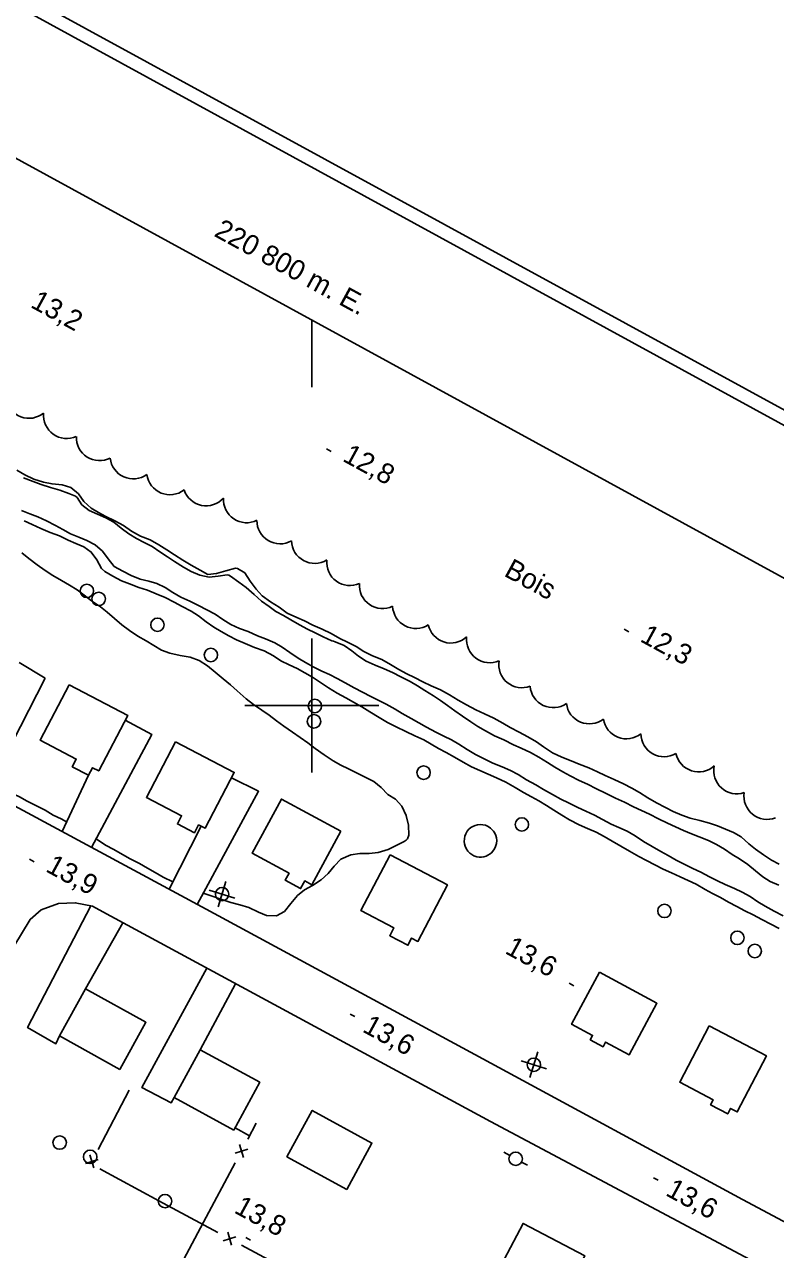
# Model space of a CAD drawing. Extents: x 219136 to 222520, y 5421589 to 5424530.
# Drawn here: x 220757.1 to 220869.2, y 5423918.8 to 5424101.6 of the extents above; entities that cross this region are included whole.
import ezdxf

# ---------------------------------------------------------------- set-up
doc = ezdxf.new("R2010")
doc.units = 0
for name, color, linetype in [('Level 19', 7, 'Continuous'), ('Level 2', 7, 'Continuous'), ('Level 21', 7, 'Continuous'), ('Level 3', 7, 'Continuous'), ('Level 31', 7, 'Continuous'), ('Level 36', 7, 'Continuous'), ('Level 37', 7, 'Continuous'), ('Level 4', 7, 'Continuous'), ('Level 44', 7, 'Continuous'), ('Level 60', 7, 'Continuous'), ('Level 61', 7, 'Continuous')]:
    doc.layers.add(name, color=color, linetype=linetype)

msp = doc.modelspace()

# ---------------------------------------------------------------- linework, layer by layer
at = {"layer": 'Level 19'}
for points in [[(220760.24, 5424004.07), (220756.33, 5424006.39)], [(220751.55, 5423987.22), (220760.24, 5424004.07)], [(220767.14, 5423978.82), (220776.12, 5423995.67), (220772.17, 5423997.8)], [(220766.7, 5423989.58), (220762.74, 5423981.19)], [(220782.92, 5423970.32), (220792.07, 5423987.2), (220788.02, 5423989.23)], [(220783.51, 5423981.98), (220778.72, 5423972.59)], [(220762.34, 5423950.72), (220761.84, 5423949.55), (220757.6, 5423951.96), (220767.02, 5423970.09)], [(220771.82, 5423967.6), (220766.23, 5423957.74)], [(220779.46, 5423941.5), (220779.02, 5423940.71), (220774.67, 5423943.01), (220784.33, 5423960.83), (220784.33, 5423960.84)], [(220788.65, 5423958.5), (220783.34, 5423948.64)]]:
    msp.add_lwpolyline(points, dxfattribs=at)
at = {"layer": 'Level 2'}
for points in [[(220788.92, 5424020.45), (220788.65, 5424020.47), (220787.17, 5424020.09), (220785.8, 5424019.68), (220784.52, 5424019.56), (220783.34, 5424020.18), (220782.01, 5424020.94), (220780.76, 5424021.66), (220779.52, 5424022.46), (220778.38, 5424023.22), (220777.21, 5424023.94), (220775.87, 5424024.69), (220774.43, 5424025.27), (220773.13, 5424026), (220771.92, 5424026.83), (220770.6, 5424027.54), (220769.28, 5424028.17), (220768.18, 5424028.78), (220767.07, 5424029.45), (220766, 5424030.43), (220765.19, 5424031.57), (220764.06, 5424032.49), (220762.76, 5424032.92), (220761.25, 5424033.06), (220759.96, 5424033.29), (220758.53, 5424033.75), (220757.21, 5424034.38), (220756.01, 5424035.11)], [(220757.08, 5424027.52), (220758.28, 5424027.01), (220759.59, 5424026.38), (220760.95, 5424025.79), (220762.35, 5424025.28), (220763.65, 5424024.68), (220764.81, 5424024.18), (220765.99, 5424023.68), (220767.11, 5424022.88), (220767.94, 5424021.7), (220768.64, 5424020.41), (220769.15, 5424019.96), (220770.33, 5424019.29), (220771.6, 5424018.61), (220772.79, 5424018.16), (220774.21, 5424017.62), (220775.49, 5424017.21), (220776.8, 5424016.67), (220778.13, 5424016.12), (220779.47, 5424015.41), (220780.67, 5424014.76), (220782, 5424014.07), (220783.11, 5424013.35), (220784.27, 5424012.49), (220785.37, 5424011.68), (220786.49, 5424011.02), (220787.65, 5424010.4), (220788.78, 5424009.81), (220790.08, 5424009.23), (220791.48, 5424008.67), (220792.89, 5424008.17), (220794.28, 5424007.42), (220795.41, 5424006.68), (220796.62, 5424006.07), (220797.83, 5424005.53), (220798.98, 5424004.89), (220800.13, 5424004.2), (220801.31, 5424003.44), (220802.49, 5424002.65), (220803.79, 5424001.84), (220805.09, 5424001.13), (220806.26, 5424000.5), (220807.48, 5423999.81)], [(220756.72, 5424022.77), (220757.81, 5424021.93), (220759.01, 5424020.98), (220760.22, 5424020.14), (220761.38, 5424019.38), (220762.66, 5424018.63), (220763.87, 5424017.93), (220764.98, 5424017.27), (220766.06, 5424016.46), (220767.15, 5424015.6), (220768.47, 5424014.7), (220769.49, 5424013.91), (220770.56, 5424012.98), (220771.69, 5424012.05), (220772.79, 5424011.2), (220774.04, 5424010.33), (220775.28, 5424009.64), (220776.43, 5424008.94), (220777.61, 5424008.23), (220778.85, 5424007.79), (220780.37, 5424007.47), (220781.84, 5424007.2), (220783.19, 5424006.7), (220784.46, 5424005.9), (220785.61, 5424004.96), (220786.79, 5424003.98), (220787.9, 5424003.06), (220788.9, 5424002.19), (220790.24, 5424000.99), (220791.31, 5424000.16), (220792.57, 5423999.29), (220793.64, 5423998.56), (220794.74, 5423997.69), (220795.85, 5423996.89)], [(220868.63, 5423976.92), (220867.42, 5423977.7), (220866.2, 5423978.55), (220865.21, 5423979.35), (220864.09, 5423980.4), (220862.94, 5423981.05), (220861.75, 5423981.57), (220860.55, 5423982.06), (220859.35, 5423982.44), (220857.94, 5423982.85), (220856.47, 5423983.2), (220855.21, 5423983.64), (220853.92, 5423984.19), (220852.8, 5423984.76), (220851.43, 5423985.48), (220850.17, 5423986.23), (220848.91, 5423987.02), (220847.77, 5423987.67), (220846.53, 5423988.31), (220845.12, 5423988.96), (220843.81, 5423989.57), (220842.65, 5423990.12), (220841.33, 5423990.7), (220839.93, 5423991.26), (220838.74, 5423991.74), (220837.31, 5423992.27), (220835.93, 5423992.94), (220834.58, 5423993.84), (220833.53, 5423994.58), (220832.25, 5423995.34), (220830.95, 5423996.02), (220829.59, 5423996.73), (220828.5, 5423997.37), (220827.16, 5423998.11), (220825.79, 5423998.73), (220824.49, 5423999.33), (220823.08, 5424000.1), (220821.84, 5424000.8), (220820.58, 5424001.58), (220819.22, 5424002.33), (220817.82, 5424002.94), (220816.58, 5424003.52), (220815.35, 5424004.15), (220814.2, 5424004.74), (220813, 5424005.37), (220811.75, 5424006.12), (220810.44, 5424006.86), (220809.07, 5424007.4), (220807.77, 5424008.03), (220806.61, 5424008.78), (220805.36, 5424009.43), (220804.21, 5424010), (220802.91, 5424010.74), (220801.57, 5424011.39), (220800.18, 5424011.96), (220798.91, 5424012.6), (220797.76, 5424013.1), (220796.36, 5424013.77), (220795.12, 5424014.68), (220793.87, 5424015.46), (220792.63, 5424016.37), (220791.71, 5424017.35), (220790.84, 5424018.55), (220790.03, 5424019.78), (220788.92, 5424020.45)], [(220807.48, 5423999.81), (220808.65, 5423999.06), (220810.09, 5423998.2), (220811.31, 5423997.48), (220812.61, 5423996.8), (220814.04, 5423996.12), (220815.4, 5423995.49), (220816.71, 5423994.85), (220817.81, 5423994.24), (220818.9, 5423993.6), (220820.06, 5423992.98), (220821.32, 5423992.3), (220822.59, 5423991.52), (220823.85, 5423990.86), (220825.09, 5423990.28), (220826.34, 5423989.73), (220827.58, 5423989.19), (220828.98, 5423988.54), (220830.35, 5423987.75), (220831.59, 5423987.03), (220832.79, 5423986.39), (220833.9, 5423985.79), (220835.03, 5423985.07), (220836.14, 5423984.39), (220837.31, 5423983.64), (220838.45, 5423982.95), (220839.92, 5423982.19), (220841.17, 5423981.65), (220842.44, 5423981.08), (220843.63, 5423980.43), (220844.86, 5423979.74), (220846.12, 5423979.02), (220847.43, 5423978.27), (220848.82, 5423977.45), (220849.95, 5423976.86), (220851.18, 5423976.24), (220852.45, 5423975.6), (220853.71, 5423975.01), (220854.96, 5423974.46), (220856.18, 5423973.9), (220857.39, 5423973.32), (220858.7, 5423972.54), (220859.8, 5423971.93), (220860.99, 5423971.34), (220862.22, 5423970.67), (220863.42, 5423970.02), (220864.63, 5423969.39), (220865.87, 5423968.75), (220867.16, 5423968.05), (220868.49, 5423967.39), (220869.76, 5423966.72)], [(220795.85, 5423996.89), (220797.11, 5423996), (220798.28, 5423995.2), (220799.42, 5423994.41), (220800.5, 5423993.6), (220801.85, 5423992.65), (220803.19, 5423991.76), (220804.33, 5423991.1), (220805.49, 5423990.53), (220806.78, 5423989.91), (220807.9, 5423989.34), (220809.27, 5423988.68), (220810.38, 5423987.74), (220811.38, 5423986.74), (220812.5, 5423986.01), (220813.47, 5423984.98), (220814.1, 5423983.59), (220814.43, 5423982.16), (220814.48, 5423980.63), (220814.3, 5423980.09), (220814.1, 5423979.89), (220813.82, 5423979.73), (220812.72, 5423979.15), (220811.42, 5423978.52), (220809.91, 5423978.06), (220808.57, 5423977.92), (220807.19, 5423977.91), (220805.85, 5423977.74), (220804.34, 5423977.09), (220803.37, 5423976.05), (220802.47, 5423974.91), (220801.41, 5423973.97), (220800.12, 5423973.16), (220798.91, 5423972.49), (220797.86, 5423971.63), (220796.86, 5423970.44), (220795.94, 5423969.29), (220794.76, 5423968.6), (220793.25, 5423968.67), (220792.05, 5423969.17), (220790.6, 5423969.85), (220789.27, 5423970.26), (220787.93, 5423970.62), (220786.61, 5423971.05), (220785.14, 5423971.53), (220783.82, 5423971.98)], [(220758.91, 5423985.02), (220757.56, 5423985.72), (220756.38, 5423986.38), (220754.99, 5423987), (220753.82, 5423987.55), (220752.22, 5423988.52)], [(220763.43, 5423982.65), (220762.59, 5423983.07), (220761.42, 5423983.62), (220760.22, 5423984.36), (220758.91, 5423985.02)], [(220779.27, 5423973.68), (220777.83, 5423974.41), (220776.62, 5423975.06), (220775.49, 5423975.74), (220774.29, 5423976.45), (220772.89, 5423977.14), (220771.79, 5423977.78), (220770.48, 5423978.52), (220769.21, 5423979.14), (220767.82, 5423980.09)], [(220869.75, 5423976.35), (220868.63, 5423976.92)]]:
    msp.add_lwpolyline(points, dxfattribs=at)
at = {"layer": 'Level 21'}
for points in [[(220909.34, 5423902.28), (220864.28, 5423926.29), (220825.56, 5423947.3), (220784.24, 5423969.61), (220739.71, 5423993.6), (220724.11, 5424001.71), (220710.35, 5424008.97), (220700.88, 5424013.04), (220692.1, 5424015.97), (220684.7, 5424017.45), (220676.08, 5424018.63), (220666.81, 5424018.72)], [(220734.33, 5423917.05), (220733.8, 5423922.07), (220734.91, 5423928.02), (220737.36, 5423933.92), (220740.72, 5423939.63), (220758.01, 5423968.08), (220759.65, 5423969.52), (220762.2, 5423970.44), (220764.72, 5423970.57), (220767.28, 5423970.04), (220768.85, 5423969.21), (220826.69, 5423937.93), (220900.24, 5423898.82)]]:
    msp.add_lwpolyline(points, dxfattribs=at)
at = {"layer": 'Level 3'}
for p, q in [((220802.21, 5424038.28), (220802.9, 5424037.9)), ((220846.61, 5424011.38), (220847.31, 5424011)), ((220757.91, 5423977.05), (220758.6, 5423976.67)), ((220838.42, 5423958.57), (220839.12, 5423958.19)), ((220805.75, 5423953.96), (220806.44, 5423953.58)), ((220850.99, 5423929.56), (220851.69, 5423929.18)), ((220790.15, 5423920.63), (220790.85, 5423920.25))]:
    msp.add_line(p, q, dxfattribs=at)
at = {"layer": 'Level 31'}
for points in [[(220763.83, 5424003.09), (220772.55, 5423998.52), (220768.21, 5423990.24), (220767.3, 5423990.72), (220766.7, 5423989.58), (220764.27, 5423990.85), (220764.87, 5423992), (220759.49, 5423994.82)], [(220779.65, 5423994.59), (220788.43, 5423990.02), (220784.09, 5423981.68), (220783.11, 5423982.19), (220782.5, 5423981.01), (220779.95, 5423982.34), (220780.58, 5423983.55), (220775.33, 5423986.29)], [(220804.35, 5423981.25), (220800.03, 5423973.26), (220798.97, 5423973.83), (220798.35, 5423972.68), (220796.05, 5423973.93), (220796.62, 5423974.98), (220791.12, 5423977.95), (220795.49, 5423986.03)], [(220824.05, 5423981.95), (220824.38, 5423982.11), (220824.74, 5423982.19), (220825.14, 5423982.23), (220825.53, 5423982.21), (220825.91, 5423982.12), (220826.31, 5423981.95), (220826.66, 5423981.72), (220826.94, 5423981.47), (220827.11, 5423981.25), (220827.32, 5423980.93), (220827.48, 5423980.6), (220827.57, 5423980.27), (220827.61, 5423979.85), (220827.57, 5423979.42), (220827.45, 5423978.94), (220827.27, 5423978.59), (220827.04, 5423978.25), (220826.81, 5423978.01), (220826.62, 5423977.86), (220826.3, 5423977.66), (220826.01, 5423977.53), (220825.7, 5423977.43), (220825.33, 5423977.37), (220824.97, 5423977.39), (220824.62, 5423977.44), (220824.21, 5423977.58), (220823.88, 5423977.75), (220823.6, 5423977.96), (220823.3, 5423978.25), (220823.03, 5423978.68), (220822.88, 5423979), (220822.78, 5423979.36), (220822.76, 5423979.73), (220822.78, 5423980.1), (220822.85, 5423980.49), (220822.99, 5423980.86), (220823.21, 5423981.23), (220823.47, 5423981.55), (220823.77, 5423981.78)], [(220811.69, 5423977.71), (220820.25, 5423973.22), (220815.84, 5423964.8), (220814.9, 5423965.29), (220814.35, 5423964.24), (220811.64, 5423965.65), (220812.26, 5423966.83), (220807.34, 5423969.41)], [(220842.93, 5423960.2), (220851.52, 5423955.57), (220847.39, 5423947.9), (220843.86, 5423949.79), (220843.48, 5423949.09), (220841.56, 5423950.13), (220841.91, 5423950.77), (220838.77, 5423952.46)], [(220771.36, 5423945.72), (220762.34, 5423950.72), (220766.23, 5423957.74), (220775.25, 5423952.74)], [(220859.31, 5423952.2), (220867.86, 5423947.73), (220863.49, 5423939.38), (220862.51, 5423939.89), (220862.09, 5423939.08), (220859.51, 5423940.44), (220859.9, 5423941.19), (220854.92, 5423943.8)], [(220788.37, 5423936.66), (220779.46, 5423941.5), (220783.34, 5423948.64), (220792.25, 5423943.79)], [(220805.22, 5423927.82), (220796.3, 5423932.69), (220800.08, 5423939.59), (220808.99, 5423934.72)], [(220836.98, 5423910.7), (220827.75, 5423915.56), (220831.54, 5423922.75), (220840.77, 5423917.88)]]:
    msp.add_lwpolyline(points, close=True, dxfattribs=at)
at = {"layer": 'Level 36'}
for p, q in [((220786.04, 5423969.95), (220787.21, 5423973.76)), ((220788.53, 5423971.27), (220784.72, 5423972.44)), ((220832.56, 5423944.5), (220833.73, 5423948.31)), ((220835.05, 5423945.82), (220831.24, 5423946.99)), ((220828.69, 5423933.36), (220829.56, 5423932.87)), ((220832.19, 5423931.42), (220831.31, 5423931.89))]:
    msp.add_line(p, q, dxfattribs=at)
for centre in [(220766.45, 5424017.09), (220768.21, 5424015.89), (220776.98, 5424012.04), (220784.96, 5424007.53), (220800.47, 5423999.92), (220800.34, 5423997.63), (220816.7, 5423989.98), (220831.36, 5423982.25), (220786.63, 5423971.86), (220852.64, 5423969.35), (220863.52, 5423965.34), (220866.12, 5423963.37), (220833.15, 5423946.41), (220762.39, 5423934.79), (220766.94, 5423932.67), (220830.44, 5423932.38), (220778.11, 5423926.07)]:
    msp.add_circle(centre, 1, dxfattribs=at)
at = {"layer": 'Level 37'}
for p, q in [((220766.88, 5423932.95), (220767.47, 5423931.04)), ((220790.48, 5423933.82), (220788.56, 5423933.24)), ((220789.81, 5423932.57), (220789.23, 5423934.49)), ((220766.22, 5423931.7), (220768.13, 5423932.29)), ((220786.78, 5423920.16), (220788.7, 5423920.74)), ((220788.03, 5423919.49), (220787.46, 5423921.41))]:
    msp.add_line(p, q, dxfattribs=at)
for points in [[(220772.77, 5423942.61), (220768.11, 5423933.76)], [(220790.73, 5423935.79), (220788.56, 5423937)], [(220790.46, 5423935.29), (220791.73, 5423937.67)], [(220768.37, 5423930.87), (220777.18, 5423926.13)], [(220783.87, 5423922.94), (220788.58, 5423931.76)], [(220777.18, 5423926.13), (220785.98, 5423921.4)], [(220779.16, 5423914.12), (220783.87, 5423922.94)], [(220789.5, 5423919.5), (220798.31, 5423914.76)]]:
    msp.add_lwpolyline(points, dxfattribs=at)
at = {"layer": 'Level 4'}
for points in [[(220756.98, 5424033.97), (220758.45, 5424033.43), (220759.61, 5424032.95), (220761.03, 5424032.49), (220762.39, 5424032.11), (220763.74, 5424031.64), (220764.77, 5424031.21), (220764.99, 5424031.01), (220765.72, 5424029.94), (220766.8, 5424029.09), (220768.01, 5424028.55), (220769.26, 5424027.99), (220770.46, 5424027.35), (220771.59, 5424026.47), (220772.69, 5424025.61), (220773.83, 5424024.91), (220774.99, 5424024.33), (220776.17, 5424023.69), (220777.34, 5424022.92), (220778.48, 5424022.17), (220779.52, 5424021.46), (220780.87, 5424020.64), (220782.01, 5424020), (220783.31, 5424019.44), (220784.71, 5424019.14), (220786.02, 5424019.27), (220787.36, 5424019.49), (220787.63, 5424019.43), (220787.9, 5424019.28), (220789.14, 5424018.38), (220790.23, 5424017.6), (220791.42, 5424016.55), (220792.52, 5424015.58), (220793.64, 5424014.76), (220794.67, 5424014.04), (220795.78, 5424013.4), (220796.9, 5424012.79)], [(220756.68, 5424029.08), (220757.94, 5424028.6), (220759.11, 5424028.13), (220760.43, 5424027.52), (220761.78, 5424026.86), (220762.86, 5424026.24), (220764, 5424025.61), (220765.25, 5424025.08), (220766.45, 5424024.61), (220767.7, 5424023.96), (220768.78, 5424023.02), (220769.62, 5424021.87), (220770.5, 5424020.74), (220771.8, 5424020.03), (220773.06, 5424019.38), (220774.41, 5424018.85), (220775.69, 5424018.53), (220776.89, 5424018.17), (220778.11, 5424017.58), (220779.29, 5424016.85), (220780.49, 5424016.17), (220781.81, 5424015.55), (220783.13, 5424014.9), (220784.37, 5424014.29), (220785.6, 5424013.64), (220786.75, 5424012.82), (220787.95, 5424012.08), (220789.23, 5424011.5), (220790.53, 5424011.01), (220791.91, 5424010.39), (220793.08, 5424009.95), (220794.51, 5424009.36)], [(220796.9, 5424012.79), (220798.18, 5424012.03), (220799.38, 5424011.38), (220800.52, 5424010.82), (220801.69, 5424010.24), (220802.99, 5424009.62), (220803.25, 5424009.59), (220803.49, 5424009.48), (220804.82, 5424008.95), (220805.99, 5424008.16), (220806.96, 5424007.35), (220808.11, 5424006.6), (220809.47, 5424006.01), (220810.81, 5424005.48), (220812.04, 5424004.93), (220813.32, 5424004.29), (220814.67, 5424003.58), (220815.78, 5424002.91), (220816.86, 5424002.21), (220818.15, 5424001.45), (220819.22, 5424000.75), (220820.27, 5424000), (220821.35, 5423999.21), (220822.51, 5423998.38), (220823.76, 5423997.55), (220824.81, 5423996.87), (220825.91, 5423996.21), (220827.28, 5423995.48), (220828.69, 5423994.85), (220830.09, 5423994.15), (220831.25, 5423993.61), (220832.63, 5423992.97), (220833.87, 5423992.28), (220835.2, 5423991.49), (220836.3, 5423990.8), (220837.47, 5423990.12), (220838.59, 5423989.48), (220839.9, 5423988.79), (220841.17, 5423988.27), (220842.5, 5423987.57), (220843.82, 5423986.91), (220845.32, 5423986.18), (220846.69, 5423985.57), (220848.04, 5423984.88), (220849.23, 5423984.35), (220850.4, 5423983.78), (220851.77, 5423983.08), (220853.11, 5423982.42), (220854.28, 5423981.9), (220855.47, 5423981.34), (220856.66, 5423980.83), (220857.84, 5423980.39), (220859.21, 5423979.84), (220860.41, 5423979.24), (220861.6, 5423978.54), (220862.73, 5423977.79), (220863.85, 5423977.1), (220865.08, 5423976.27), (220866.22, 5423975.31), (220867.33, 5423974.46), (220868.4, 5423973.76), (220869.71, 5423973.18)], [(220794.51, 5424009.36), (220795.59, 5424008.72), (220796.75, 5424007.9), (220797.97, 5424007.08), (220799.09, 5424006.41), (220800.32, 5424005.72), (220801.51, 5424005.13), (220802.67, 5424004.61), (220803.78, 5424004.03), (220804.98, 5424003.39), (220806.34, 5424002.61), (220807.57, 5424001.98), (220808.81, 5424001.35), (220809.94, 5424000.79), (220811.13, 5424000.21), (220812.44, 5423999.46), (220813.52, 5423998.8), (220814.86, 5423998.04), (220815.97, 5423997.43), (220817.15, 5423996.78), (220818.54, 5423996.03), (220819.73, 5423995.42), (220820.85, 5423994.85), (220821.93, 5423994.21), (220823.21, 5423993.43), (220824.46, 5423992.71), (220825.63, 5423992.09), (220827.04, 5423991.4), (220828.42, 5423990.84), (220829.68, 5423990.28), (220830.81, 5423989.68), (220832.07, 5423988.9), (220833.42, 5423988.17), (220834.57, 5423987.47), (220835.92, 5423986.73), (220837.16, 5423986.04), (220838.3, 5423985.46), (220839.7, 5423984.78), (220840.9, 5423984.22), (220842.2, 5423983.62), (220843.38, 5423982.99), (220844.7, 5423982.3), (220845.85, 5423981.8), (220847.09, 5423981.24), (220848.29, 5423980.57), (220849.53, 5423979.71), (220850.79, 5423978.98), (220852.1, 5423978.23), (220853.2, 5423977.61), (220854.4, 5423976.93), (220855.57, 5423976.32), (220856.87, 5423975.69), (220858.06, 5423975.13), (220859.38, 5423974.45), (220860.54, 5423973.86), (220861.7, 5423973.31), (220863.1, 5423972.7), (220864.25, 5423972.16), (220865.42, 5423971.5), (220866.57, 5423970.72), (220867.65, 5423970.05), (220869.01, 5423969.34), (220870.33, 5423968.61)]]:
    msp.add_lwpolyline(points, dxfattribs=at)
at = {"layer": 'Level 44'}
for centre, start, end in [((220757.79, 5424046.29), 189.5072, 309.5072), ((220763.44, 5424043.28), 174.4378, 294.4378), ((220768.34, 5424039.98), 177.4801, 297.4801), ((220773.38, 5424037.25), 185.7373, 305.7373), ((220778.84, 5424034.89), 187.5597, 307.5597), ((220784.24, 5424033.24), 198.4655, 318.4655), ((220790.29, 5424030.72), 176.26, 296.26), ((220795.28, 5424027.57), 179.3092, 299.3092), ((220800.44, 5424024.65), 181.5617, 301.5617), ((220805.7, 5424021.34), 174.1888, 294.1888), ((220810.57, 5424017.92), 175.5623, 295.5623), ((220815.53, 5424014.94), 182.4167, 302.4167), ((220820.77, 5424012.77), 192.6495, 312.6495), ((220826.56, 5424009.84), 173.651, 293.651), ((220831.37, 5424006.1), 170.6704, 290.6704), ((220836.04, 5424003.13), 184.4844, 304.4844), ((220841.44, 5424000.72), 187.3377, 307.3377), ((220846.97, 5423998.48), 188.4251, 308.4251), ((220852.58, 5423995.8), 180.6725, 300.6725), ((220857.74, 5423993.55), 192.1797, 312.1797), ((220863.45, 5423990.28), 168.2977, 288.2977), ((220867.96, 5423986.46), 171.0824, 291.0824)]:
    msp.add_arc(centre, 3.46, start, end, dxfattribs=at)
at = {"layer": 'Level 60'}
for points in [[(219135.93, 5422982.66), (219981.09, 5424529.89), (222519.95, 5423143.06), (221674.79, 5421595.83), (219135.93, 5422982.66)], [(219138.65, 5422983.46), (219981.9, 5424527.19), (222517.24, 5423142.28), (221673.99, 5421598.55), (219138.65, 5422983.46)]]:
    msp.add_lwpolyline(points, dxfattribs=at)
msp.add_lwpolyline([(219164.83, 5422989.67), (219989.85, 5424500.03), (222033.74, 5423383.57), (221208.72, 5421873.21)], close=True, dxfattribs=at)
at = {"layer": 'Level 61'}
msp.add_line((220800, 5424057.49), (220800, 5424047.49), dxfattribs=at)
for points in [[(220800, 5424010), (220800, 5424000), (220800, 5423990)], [(220790, 5424000), (220800, 5424000), (220810, 5424000)]]:
    msp.add_lwpolyline(points, dxfattribs=at)

# ---------------------------------------------------------------- texts
at = {"layer": 'Level 3'}
for s, p in [('13,2', (220757.89, 5424059.48)), ('12,8', (220804.45, 5424036.54)), ('12,3', (220848.85, 5424009.64)), ('13,9', (220760.15, 5423975.32)), ('13,6', (220828.69, 5423963.11)), ('13,6', (220807.42, 5423951.41)), ('13,6', (220852.66, 5423927)), ('13,8', (220788.26, 5423924.42))]:
    msp.add_text(s, height=3, rotation=331.383, dxfattribs=at).set_placement(p)
at = {"layer": 'Level 44'}
msp.add_text('Bois', height=3, rotation=331.3547, dxfattribs=at).set_placement((220828.54, 5424019.4))
at = {"layer": 'Level 61'}
msp.add_text('220 800 m. E.', height=3, rotation=331.3547, dxfattribs=at).set_placement((220785.28, 5424070.09))

doc.saveas('drawing.dxf')
